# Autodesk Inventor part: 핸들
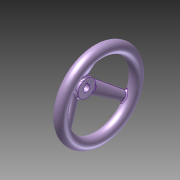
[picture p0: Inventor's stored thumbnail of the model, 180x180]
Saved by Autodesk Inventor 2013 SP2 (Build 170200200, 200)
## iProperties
Created: 2024-07
Part Number: 핸들
Material: Generic
Document SubType Name: Modeling
Designer: 601
Density: 1 g/cm^3
Author: 601
변환 표준: STEP AP214IS
전처리기: Build: 200, Release: 2013 SP2 Update 6 - Date: Thu 07/17/2014
전송 단위: 밀리미터
불확실성: 0.01
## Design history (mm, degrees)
node "핸들1"
node "솔리드1"
node "기준1"
